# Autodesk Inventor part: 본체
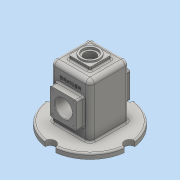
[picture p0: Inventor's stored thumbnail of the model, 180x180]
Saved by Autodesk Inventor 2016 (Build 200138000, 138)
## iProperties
Created: 2018-07
Part Number: 본체
Material: 일반
Document SubType Name: Modeling
Designer: 2-PC02
Density: 1 g/cm^3
Appearance: 기본값
Mass: 461.374 g
Surface Area: 953.172 cm^2
Volume: 461.374 cm^3
Author: 2-PC02
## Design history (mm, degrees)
sketch "스케치1"
  geometry: C1 r 75 at (0, 0); 1 further point
  constraints: 1 centre point, 1 coincident
  dimensions: "d0" = 150 diameter of C1
extrude "돌출1" new body sketch "스케치1" distance "d1" = 10; taper "d2" = 0 deg
sketch "스케치2"
  geometry: L1 (37, -37)-(-37, -37); L2 (-37, -37)-(-37, 37); L3 (-37, 37)-(37, 37); L4 (37, 37)-(37, -37); L5 (37, -37)-(-37, 37); L6 (-37, -37)-(37, 37); 1 further point
  constraints: 12 end point, 2 midpoint, 2 parallel, 1 horizontal, 1 perpendicular
  dimensions: "d3" = 74 distance of L2.end L3.end; "d4" = 74 distance of L1.end L2.end
extrude "돌출2" join sketch "스케치2" distance "d5" = 100; taper "d6" = 0 deg
sketch "스케치3"
  geometry: L1 (20, -20)-(-20, -20); L2 (-20, -20)-(-20, 20); L3 (-20, 20)-(20, 20); L4 (20, 20)-(20, -20); L5 (20, -20)-(-20, 20); L6 (-20, -20)-(20, 20); 1 further point
  constraints: 12 end point, 2 midpoint, 2 parallel, 1 horizontal, 1 perpendicular
  dimensions: "d7" = 40 distance of L2.end L3.end; "d8" = 40 distance of L3.end L1.start
extrude "돌출3" join sketch "스케치3" distance "d9" = 7; taper "d10" = 0 deg
sketch "스케치4"
  geometry: C1 r 17.5 at (0, 0); 1 further point
  constraints: 1 centre point, 1 coincident
  dimensions: "d11" = 35 diameter of C1
extrude "돌출4" join sketch "스케치4" distance "d12" = 3; taper "d13" = 0 deg
sketch "스케치5"
  geometry: L1 (62, 20)-(12, 20); L2 (12, 20)-(12, 70); L3 (12, 70)-(62, 70); L4 (62, 70)-(62, 20); L5 (62, 20)-(12, 70); L6 (12, 20)-(62, 70); L7 (-38, -10)-(112, -10) reference; 2 further points
  constraints: 12 end point, 2 midpoint, 2 parallel, 1 horizontal, 1 perpendicular
  dimensions: "d14" = 50 distance of L2.end L3.end; "d15" = 50 distance of L1.end L2.end; "d16" = 55 distance from line of L7 point (37, 45)
extrude "돌출5" join sketch "스케치5" distance "d17" = 13; taper "d18" = 0 deg
sketch "스케치7"
  geometry: 2 further points
  constraints: 1 coincident
hole "구멍1" sketch "스케치7" at (0, 0) diameter "d23" = 21; stored, may be unused: countersink angle "d27" = 90 deg, drill point angle "d29" = 0 deg; dims "d24" = 6, "d25" = 28, "d26" = 4, "d28" = 15
sketch "스케치12"
  geometry: L1 (-38, -10)-(112, -10) reference; 2 further points
  dimensions: "d54" = 55 distance from line of L1 point (37, 45)
hole "구멍2" sketch "스케치12" at (37, 45) diameter "d55" = 32; stored, may be unused: countersink angle "d59" = 110 deg, drill point angle "d61" = 0 deg; dims "d56" = 6, "d57" = 64, "d58" = 4, "d60" = 100
sketch "스케치13"
  geometry: L1 (10.5, 105)-(-10.5, 105) reference; L2 (-32, 105)-(-32, 80); L3 (-32, 80)-(-25, 77.452); L4 (-32, 105)-(0, 105); L5 (0, 0)-(0, 105); L6 (-37, 10)-(-37, 110) reference; L7 (-50, 39)-(-50, 71) reference; L8 (-25, 77.452)-(0, 77.452)
  constraints: 10 end point, 2 perpendicular, 1 midpoint, 1 point on line
  dimensions: "d62" = 5 distance between parallel lines of L6 L2
revolve "회전3" sketch "스케치13" stored, may be unused: angle "d69" = 90 deg
sketch "스케치14"
  geometry: L1 (-75, 0)-(75, 0) reference; L2 (-32, 0)-(-32, 30); L3 (-32, 30)-(-25, 32.548); L4 (-25, 32.548)-(0, 32.548); L5 (0, 32.548)-(0, 0); L6 (-32, 0)-(0, 0); L7 (-50, 39)-(-50, 71) reference; L8 (-50, 55)-(0, 55)
  constraints: 12 end point, 3 perpendicular, 1 collinear, 1 horizontal, 1 midpoint, 1 point on line
  dimensions: "d70" = 32 distance between parallel lines of L5 L2; "d71" = 110 deg angle of L2 L3; "d72" = 25 distance from line of L2.end L8; "d73" = 7 distance from line of L2 L3.end
revolve "회전4" sketch "스케치14" stored, may be unused: angle "d74" = 90 deg
sketch "스케치15"
  geometry: 2 further points
  constraints: 1 coincident
hole "구멍3" sketch "스케치15" at (0, 0) diameter "d75" = 50; stored, may be unused: countersink angle "d79" = 110 deg, drill point angle "d81" = 0 deg; dims "d76" = 6, "d77" = 64, "d78" = 4, "d80" = 50
fillet "모깎기1" dims "d82" = 8
sketch "스케치17"
  geometry: C1 r 10 at (0, 75); C2 r 10 at (75, 0); C3 r 10 at (0, -75); C4 r 10 at (-75, 0); A1 r 75 centre (0, 0) between (0, 75) and (75, 0) reference; 1 further point
  constraints: 4 centre point, 4 point on circle
  dimensions: "d84" = 20 diameter of C1; "d85" = 20 diameter of C2; "d86" = 20 diameter of C3; "d87" = 20 diameter of C4
extrude "돌출8" cut sketch "스케치17" stored distance "d88" = 25; taper "d89" = 0 deg
sketch "스케치18"
  geometry: L1 (37, 61)-(37, 29) reference; L2 (57, 25)-(17, 65); L3 (17, 25)-(57, 65); 6 further points
  constraints: 4 coincident, 4 end point, 3 midpoint
  dimensions: "d90" = 40 distance of L2.end L3.end; "d91" = 40 distance of L3.start L2.end
hole "구멍4" sketch "스케치18" at (17, 65), (57, 65), (57, 25), (17, 25) diameter "d92" = 3.459; stored, may be unused: countersink angle "d96" = 110 deg, drill point angle "d98" = 118 deg; dims "d93" = 8, "d94" = 64, "d95" = 4, "d97" = 10
fillet "모깎기3" dims "d99" = 8
fillet "모깎기4" dims "d100" = 3
fillet "모깎기5" dims "d101" = 3
fillet "모깎기6" dims "d102" = 3
fillet "모깎기7" dims "d103" = 3
fillet "모깎기8" dims "d104" = 3
fillet "모깎기9" dims "d105" = 3
fillet "모깎기10" dims "d106" = 3
fillet "모깎기11" dims "d107" = 3
fillet "모깎기12" dims "d112" = 3
chamfer "모따기1" distance "d113" = 1; stored, may be unused: second distance "d114" = 2, angle "d115" = 45 deg
sketch "스케치21"
  geometry: L1 (8.838, -8.792)-(49.162, -8.792); L2 (49.162, -8.792)-(49.162, -15.208); L3 (49.162, -15.208)-(8.838, -15.208); L4 (8.838, -15.208)-(8.838, -8.792); L5 (8.838, -12)-(49.162, -12); L6 (29, -8.792)-(29, -15.208); L7 (46.5, 18)-(11.5, 18) reference; L8 (-8, 0)-(-8, -89) reference; 1 further point
  constraints: 4 end point, 4 midpoint, 2 other
  dimensions: "d117" = 40.32343 distance between parallel lines of L4 L2; "d118" = 6.41564 distance between parallel lines of L3 L1; "d119" = 30 distance between parallel lines of L5 L7; "d120" = 37 distance between parallel lines of L8 L6
feature "엠보싱1" sketch "스케치21" dims "d10" = 0, "d121" = 0.5, "d122" = 0
node "솔리드1"
mirror "대칭1"
mirror "대칭4"
